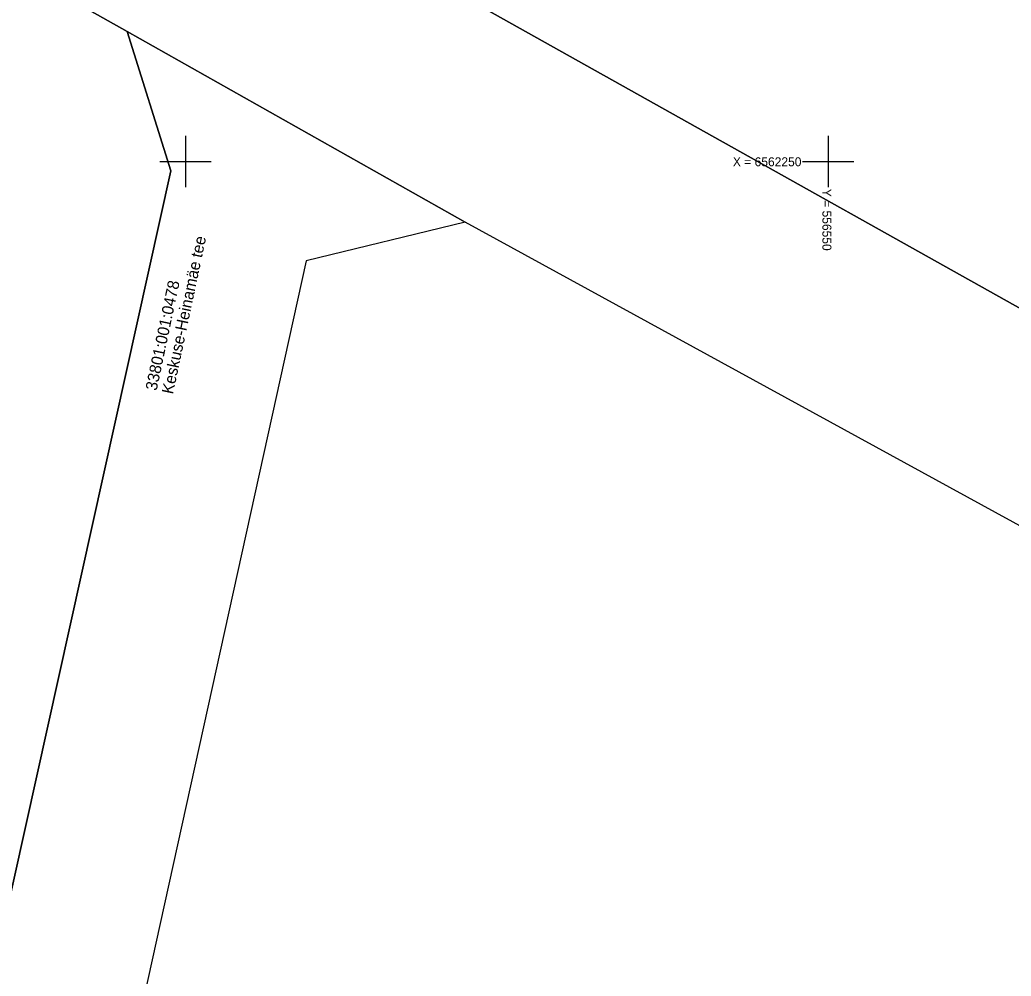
# Model space of a CAD drawing. Extents: x 551623 to 559850, y 6561220 to 6567135.
# Drawn here: x 556487.1 to 556564.2, y 6562186.7 to 6562261 of the extents above; entities that cross this region are included whole.
import ezdxf

# ---------------------------------------------------------------- set-up
doc = ezdxf.new("R2010")
doc.units = 0
doc.layers.add('PIIR', color=7, linetype='Continuous')
doc.layers.add('VORK', color=7, linetype='Continuous')

msp = doc.modelspace()

# ---------------------------------------------------------------- linework, layer by layer
at = {"layer": 'PIIR'}
for points in [[(556213.62, 6562411.94), (556232.56, 6562405.55), (556232.11, 6562403.44), (556281.46, 6562387.24), (556284.87, 6562386.12), (556330.08, 6562365.46), (556374.38, 6562345.21), (556387, 6562338.15), (556437.1, 6562310.11), (556489.06, 6562281.04), (556523.22, 6562261.92), (556579.7, 6562230.32), (556650.45, 6562190.73), (556673.82, 6562177.69), (556694.17, 6562166.24)], [(556687.52, 6562153.65), (556662.03, 6562168.17), (556644.14, 6562178.32), (556639.8, 6562180.7), (556521.76, 6562245.28), (556495.46, 6562260.13), (556444.89, 6562288.53), (556379.74, 6562323.29), (556376.12, 6562325.12), (556330.04, 6562347.99), (556327.94, 6562348.96), (556306.93, 6562358.44), (556286.98, 6562366.81), (556260.76, 6562376.89), (556235.24, 6562386), (556214.75, 6562392.6)], [(556439.54, 6561968.85), (556459.07, 6562066.71), (556462.33, 6562081.64), (556485.81, 6562190.42), (556498.86, 6562249.27), (556495.46, 6562260.13), (556521.76, 6562245.28), (556509.4, 6562242.29), (556467.37, 6562051.68), (556471.33, 6562042.96), (556640.86, 6562172.27), (556639.8, 6562180.7), (556644.14, 6562178.32), (556662.03, 6562168.17), (556651.25, 6562165.99), (556471.34, 6562027.97), (556460.76, 6562016.69)]]:
    msp.add_lwpolyline(points, dxfattribs=at)
for points in [[(556619.64, 6562301.13), (556579.7, 6562230.32), (556523.22, 6562261.92), (556520.17, 6562273.55), (556529.17, 6562310.34), (556564.83, 6562309.05), (556607.77, 6562305.94)], [(556437.95, 6562207.26), (556444.89, 6562288.53), (556495.46, 6562260.13), (556498.86, 6562249.27), (556485.81, 6562190.42), (556482.55, 6562191.68), (556442.92, 6562205.7)]]:
    msp.add_lwpolyline(points, close=True, dxfattribs=at)
at = {"layer": 'VORK'}
for p, q in [((556500, 6562252), (556500, 6562248)), ((556550, 6562252), (556550, 6562248)), ((556498, 6562250), (556502, 6562250)), ((556548, 6562250), (556552, 6562250))]:
    msp.add_line(p, q, dxfattribs=at)

# ---------------------------------------------------------------- texts
at = {"layer": 'PIIR'}
for s, p in [('Keskuse-Heinamäe tee', (556499.028, 6562231.87)), ('33801:001:0478', (556497.757, 6562232.14))]:
    msp.add_text(s, height=0.9, rotation=78.05024, dxfattribs=at).set_placement(p)
at = {"layer": 'VORK'}
msp.add_text('X = 6562250', height=0.7, dxfattribs=at).set_placement((556542.584, 6562249.636))
msp.add_text('Y = 556550 ', height=0.7, rotation=270, dxfattribs=at).set_placement((556549.549, 6562247.886))

doc.saveas('drawing.dxf')
